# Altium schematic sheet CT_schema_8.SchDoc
size 251 x 159 mm
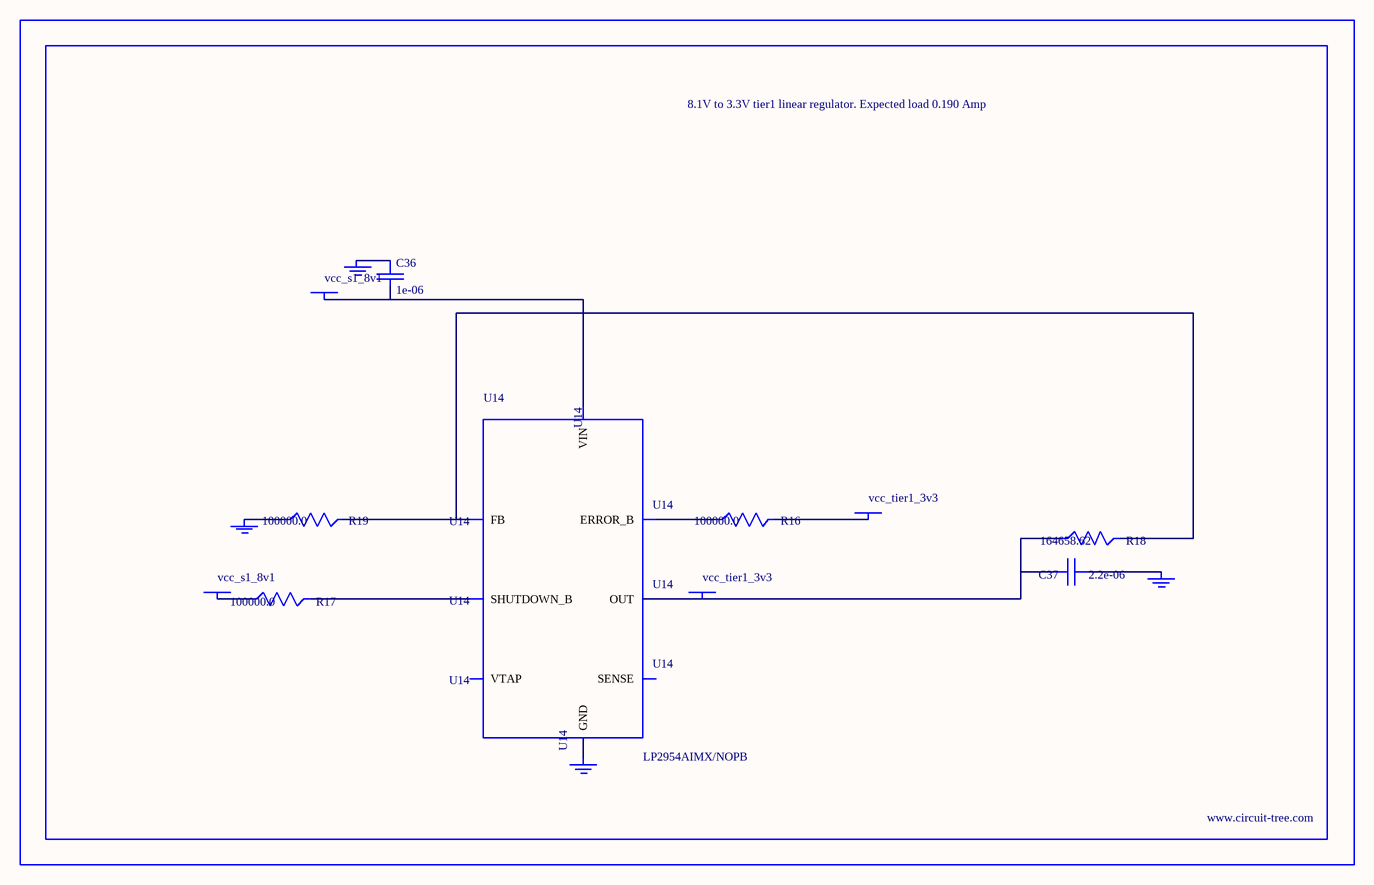
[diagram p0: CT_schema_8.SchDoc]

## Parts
BORDER7  (no value)
C36  1e-06  [EXV-9B]
C37  2.2e-06  [EXV-9B]
GND_INSTANCE_7_0  (no value)
GND_INSTANCE_7_1  (no value)
GND_INSTANCE_7_2  (no value)
GND_INSTANCE_7_3  (no value)
POWER_INSTANCE_7_0  vcc_s1_8v1
POWER_INSTANCE_7_1  vcc_tier1_3v3
POWER_INSTANCE_7_2  vcc_s1_8v1
POWER_INSTANCE_7_3  vcc_tier1_3v3
R16  100000.0  [R0603]
R17  100000.0  [R0603]
R18  164658.62  [R0603]
R19  100000.0  [R0603]
U14  LP2954AIMX/NOPB  [LP2954]

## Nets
NetC36_1: C36.1 GND_INSTANCE_7_2.0(GND)
NetC36_2: C36.2 POWER_INSTANCE_7_2.0(PWR) U14.8(VIN)
NetC37_1: C37.1 GND_INSTANCE_7_0.0(GND)
NetC37_2: C37.2 POWER_INSTANCE_7_3.0(PWR) R18.1 U14.1(OUT)
NetGND_INSTANCE_7_1_0: GND_INSTANCE_7_1.0(GND) R19.1
NetGND_INSTANCE_7_3_0: GND_INSTANCE_7_3.0(GND) U14.4(GND)
NetPOWER_INSTANCE_7_0_0: POWER_INSTANCE_7_0.0(PWR) R17.1
NetPOWER_INSTANCE_7_1_0: POWER_INSTANCE_7_1.0(PWR) R16.2
NetR16_1: R16.1 U14.5(ERROR_B)
NetR17_2: R17.2 U14.3(SHUTDOWN_B)
NetR18_2: R18.2 R19.2 U14.7(FB)

Not connected (* = marked no-connect by the designer): U14 2(SENSE) 6(VTAP)

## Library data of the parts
BORDER7 = BORDER_PAGE7
C36 = EDK105M050A9BAA
C37 = EDK225M050A9BAA
GND_INSTANCE_7_0-GND_INSTANCE_7_3 = GND
POWER_INSTANCE_7_0-POWER_INSTANCE_7_3 = PWR
R16 R17 R19 = RC0603JR-07100KL
R18 = R18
